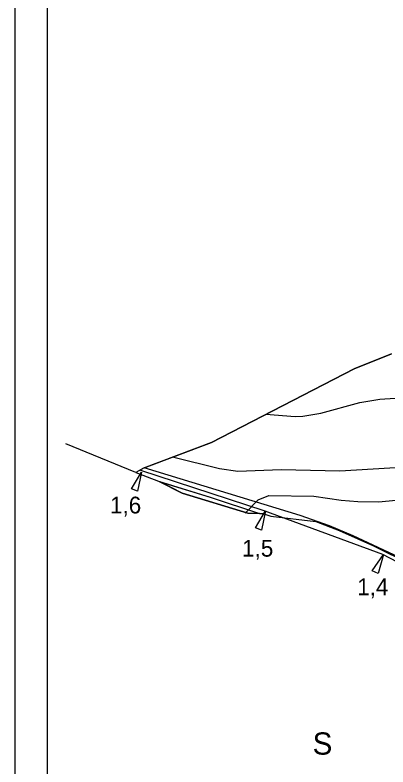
# Model space of a CAD drawing. Extents: x -684583 to -680383, y -1157874 to -1154904.
# Drawn here: x -684583 to -684294, y -1157579 to -1156997 of the extents above; entities that cross this region are included whole.
import ezdxf

# ---------------------------------------------------------------- set-up
doc = ezdxf.new("R2010")
doc.units = 0
for name, color, linetype in [('01_OBVOD PÚ', 7, 'Continuous'), ('01_SPRÁV_HRANICE', 7, 'Continuous'), ('01_VRSTEVNICE', 7, 'Continuous'), ('02_KULTURY STAV', 7, 'Continuous'), ('05_VHO_V_TOK', 7, 'Continuous'), ('Vrstva 60', 7, 'Continuous'), ('Vrstva 63', 7, 'Continuous')]:
    doc.layers.add(name, color=color, linetype=linetype)

msp = doc.modelspace()

# ---------------------------------------------------------------- linework, layer by layer
at = {"layer": '01_OBVOD PÚ'}
msp.add_lwpolyline([(-684291.25, -1157258.99), (-684320, -1157270.76), (-684430.8, -1157327.63), (-684483.35, -1157347.57), (-684489.27, -1157350.87), (-684471.72, -1157357.58), (-684453.45, -1157367.06), (-684402.43, -1157382.51), (-684390.94, -1157382.84), (-684384.77, -1157384.77), (-684349.88, -1157389), (-684331.72, -1157395.91), (-684305.22, -1157407.64), (-684276.36, -1157421.86)], dxfattribs=at)
at = {"layer": '01_SPRÁV_HRANICE'}
for points in [[(-684291.25, -1157258.99), (-684320, -1157270.76), (-684430.8, -1157327.63), (-684483.35, -1157347.57), (-684489.27, -1157350.87), (-684471.72, -1157357.58), (-684453.45, -1157367.06), (-684402.43, -1157382.51), (-684390.94, -1157382.84), (-684384.77, -1157384.77), (-684349.88, -1157389), (-684331.72, -1157395.91), (-684305.22, -1157407.64), (-684276.36, -1157421.86)], [(-684489.27, -1157350.87), (-684543.68, -1157328.89)]]:
    msp.add_lwpolyline(points, dxfattribs=at)
at = {"layer": '01_VRSTEVNICE'}
for points in [[(-684388.46, -1157305.9), (-684365.81, -1157307.52), (-684359.82, -1157307.23), (-684345.84, -1157304.95), (-684315.6, -1157296.68), (-684300.19, -1157294.11), (-684288.21, -1157293.39)], [(-684257.97, -1157345.46), (-684331.29, -1157350.02), (-684376.65, -1157349.03), (-684410.32, -1157350.31), (-684424.58, -1157348.03), (-684460.84, -1157339.03)], [(-684404.67, -1157382.45), (-684394.62, -1157372.13), (-684386.35, -1157368.85), (-684351.26, -1157369.42), (-684330.15, -1157372.42), (-684317.31, -1157373.42), (-684301.33, -1157373.7), (-684273.95, -1157371.14)]]:
    msp.add_lwpolyline(points, dxfattribs=at)
at = {"layer": '02_KULTURY STAV'}
for points in [[(-684206.82, -1157453.3), (-684320.88, -1157400.08), (-684339.32, -1157392.19), (-684361.97, -1157384.23), (-684482.93, -1157347.41), (-684430.8, -1157327.63), (-684320, -1157270.76), (-684291.25, -1157258.99)], [(-684206.82, -1157453.3), (-684320.88, -1157400.08), (-684339.32, -1157392.19), (-684361.97, -1157384.23), (-684482.93, -1157347.41), (-684489.27, -1157350.87), (-684471.72, -1157357.58), (-684431.7, -1157370.11), (-684393.54, -1157382.77), (-684390.94, -1157382.84), (-684386.13, -1157384.31), (-684384.77, -1157384.77), (-684349.88, -1157389), (-684331.72, -1157395.91), (-684305.22, -1157407.64), (-684276.36, -1157421.86)]]:
    msp.add_lwpolyline(points, dxfattribs=at)
msp.add_lwpolyline([(-684470.55, -1157358.19), (-684431.7, -1157370.11), (-684393.54, -1157382.77), (-684402.43, -1157382.51), (-684453.45, -1157367.06)], close=True, dxfattribs=at)
at = {"layer": '05_VHO_V_TOK'}
for points in [[(-684488.1, -1157365.47), (-684492.75, -1157363.61), (-684484.85, -1157350.61)], [(-684391.86, -1157395.57), (-684396.52, -1157393.74), (-684388.69, -1157380.7)], [(-684301.5, -1157429.13), (-684306.03, -1157427.01), (-684297.41, -1157414.48)]]:
    msp.add_lwpolyline(points, close=True, dxfattribs=at)
msp.add_lwpolyline([(-684485.8, -1157349.07), (-684390.19, -1157380.48), (-684298.19, -1157414.2), (-684257.11, -1157435.56)], dxfattribs=at)
at = {"layer": 'Vrstva 60'}
for p, q in [((-684582.97, -1157873.79), (-684582.97, -1154903.79)), ((-684557.97, -1154928.79), (-684557.97, -1157848.79))]:
    msp.add_line(p, q, dxfattribs=at)

# ---------------------------------------------------------------- texts
at = {"layer": '05_VHO_V_TOK'}
for s, p in [('1,6', (-684509.32, -1157382.69)), ('1,5', (-684406.94, -1157416.14)), ('1,4', (-684317.74, -1157445.98))]:
    msp.add_text(s, height=13, dxfattribs=at).set_placement(p)
at = {"layer": 'Vrstva 63'}
msp.add_text('S', height=17.23, rotation=359.44123, dxfattribs=at).set_placement((-684352.4, -1157569.42))

doc.saveas('drawing.dxf')
